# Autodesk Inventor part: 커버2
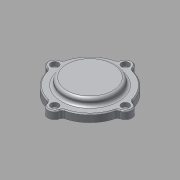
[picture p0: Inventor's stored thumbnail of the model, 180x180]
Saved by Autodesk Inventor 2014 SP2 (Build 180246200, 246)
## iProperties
Company: 한국ATC센터
Created: 2015-12
Part Number: 커버2
Document SubType Name: Modeling
Designer: mdu
Density: 2.71 g/cm^3
Material: 알루미늄 6061
Appearance: 알루미늄 - 평지
Author: mdu
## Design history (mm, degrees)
sketch "스케치1"
  geometry: C1 r 1.621 at (0, 6.75) reference; C2 r 1.621 at (-37, -30.25) reference; C3 r 1.621 at (0, -67.25) reference; C4 r 1.621 at (37, -30.25) reference; C5 r 10 at (0, -30.25) reference; C6 r 12 at (0, -30.25); C7 r 24.5 at (0, -30.25) reference; A1 r 3 centre (-38.77, -20.408) between (-38.239, -23.361) and (-35.862, -21.146) reference; A2 r 7 centre (-37, -30.25) between (-38.239, -23.361) and (-38.239, -37.139) reference; A3 r 3 centre (-38.77, -40.092) between (-35.862, -39.354) and (-38.239, -37.139) reference; A4 r 37 centre (0, -30.25) between (-35.862, -39.354) and (-9.104, -66.113) reference; A5 r 3 centre (-9.842, -69.02) between (-6.889, -68.489) and (-9.104, -66.113) reference; A6 r 7 centre (0, -67.25) between (-6.889, -68.489) and (6.889, -68.489) reference; A7 r 3 centre (9.842, -69.02) between (9.104, -66.112) and (6.889, -68.489) reference; A8 r 37 centre (0, -30.25) between (9.104, -66.112) and (35.863, -39.354) reference; A9 r 3 centre (38.77, -40.092) between (38.239, -37.139) and (35.863, -39.354) reference; A10 r 7 centre (37, -30.25) between (38.239, -37.139) and (38.239, -23.361) reference; A11 r 3 centre (38.77, -20.408) between (35.863, -21.146) and (38.239, -23.361) reference; A12 r 37 centre (0, -30.25) between (35.863, -21.146) and (9.104, 5.612) reference; A13 r 3 centre (9.842, 8.52) between (6.889, 7.989) and (9.104, 5.612) reference; A14 r 7 centre (0, 6.75) between (6.889, 7.989) and (-6.889, 7.989) reference; A15 r 3 centre (-9.842, 8.52) between (-9.104, 5.612) and (-6.889, 7.989) reference; A16 r 37 centre (0, -30.25) between (-9.104, 5.612) and (-35.862, -21.146) reference; 1 further point
  constraints: 1 centre point, 1 coincident
  dimensions: "d2" = 2 radial gap between concentric circles of C6 C5
extrude "돌출1" new body sketch "스케치1" distance "d0" = 8; taper "d1" = 0 deg
sketch "스케치2"
  geometry: C1 r 23.5 at (0, -30.25) reference; C2 r 12 at (0, -30.25) reference; 1 further point
extrude "돌출2" join sketch "스케치2" distance "d4" = 5; taper "d5" = 0 deg
sketch "스케치3"
  geometry: C1 r 23.5 at (0, 0) reference; C2 r 20.5 at (0, 0); 1 further point
  constraints: 1 centre point
  dimensions: "d6" = 3 radial gap between concentric circles of C2 C1
node "작업 평면1"
extrude "돌출3" join sketch "스케치3" stored distance "d7" = 5; taper "d8" = 0 deg
fillet "모깎기1" dims "d9" = 3
sketch "스케치4"
  geometry: C1 r 12 at (0, -30.25) reference; C2 r 27 at (0, -30.25); 1 further point
  constraints: 1 centre point
  dimensions: "d10" = 15 radial gap between concentric circles of C1 C2
extrude "돌출4" join sketch "스케치4" distance "d11" = 7; taper "d12" = 0 deg
fillet "모깎기2" dims "d13" = 3
chamfer "모따기1" distance "d14" = 1; stored, may be unused: second distance "d15" = 2, angle "d16" = 45 deg
node "작업점1"
  node "작업축1"
chamfer "모따기2" distance "d24" = 1; stored, may be unused: second distance "d25" = 2, angle "d26" = 45 deg
hole "구멍6" diameter "d43" = 4.5; stored, may be unused: countersink angle "d47" = 90 deg, drill point angle "d49" = 118 deg; dims "d41" = 10, "d42" = 10, "d44" = 6, "d45" = 8, "d46" = 4.4, "d48" = 8
fillet "모깎기4" dims "d60" = 3
node "솔리드1"
pattern_circular "원형 패턴1" dims angle "d51" = 360 deg
node "참조1"
node "참조2"
